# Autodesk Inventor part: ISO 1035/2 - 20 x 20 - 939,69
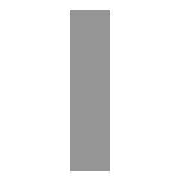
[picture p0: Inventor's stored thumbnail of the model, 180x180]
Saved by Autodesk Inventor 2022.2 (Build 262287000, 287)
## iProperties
IsCustomPart: 1
Created: 2025-02
Part Number: ISO 1035/2 - 20 x 20 - 939,69
Material: Acciaio, Dolce
Description: Barre in acciaio laminate a caldo - Parte 2: barre quadre
Document SubType Name: Modeling
Standard: ISO 1035/2
Designer: 18907419
Standard Revision: First edition 1980-10-15
Standards Organization: ISO
Language: it-IT
Size Designation: 20x 20
Categories: <MemberInstance><Categories><Category DisplayName="Forme strutturali" InternalName="089c4875-fa83-4c05-b084-43b9cc11f5ed" Mnemonic="GRDR"><CategoryParameter Dis
Stock Number: 20x 20
Density: 7.85 g/cm^3
Appearance: Semilucidato
_CCFamilyMember: 168
_CCFamilyDisplayName: ISO 1035/2 - 1980 - Barre in acciaio laminate a caldo - Parte 2: barre quadre
_FrameMemberDoc: Frame Member File
_Version: 15.0.0
_GetPNFromCC: 1
G_L: 939,693 mm
G_W: 20,000 mm
G_H: 20,000 mm
+9CC89346-D58E-49AB-A0AD-2FBC8E4EAC78+CUTDETAIL1: Angolo retto 45,00 gr
+C2A38097-E8B2-4737-A28E-4EEA481CF980+CUTDETAIL2: Angolo di taglio 90,00 gr
Author: 18907419
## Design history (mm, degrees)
node "Piano iniziale"
node "Piano finale"
sketch "Schizzo"
  geometry: L1 (10, -10)-(-10, -10); L2 (-10, -10)-(-10, 10); L3 (-10, 10)-(10, 10); L4 (10, 10)-(10, -10); L5 (-6, 0)-(8, 0); L6 (0, -30)-(0, 40); L7 (0, 54)-(0, -44) reference; L8 (-14, 0)-(14, 0) reference
  constraints: 12 end point, 2 collinear, 2 parallel, 1 horizontal, 1 perpendicular
  dimensions: "d0" = 20 distance between parallel lines of L3 L1 (= G_W); "d1" = 20 distance between parallel lines of L4 L2 (= G_H); "d4" = 10 distance between parallel lines of L6 L4 (= 0.5 x d1); "d5" = 10 distance between parallel lines of L5 L3 (= 0.5 x d0)
extrude "Corpo" new body sketch "Schizzo" stored distance "d2" = 939.69262 (= G_L); taper "d3" = 0 deg
node "Driven Length"
  sketch "Sketch3"
    geometry: L1 (0, 0)-(10, 0) reference
    constraints: 2 end point, 1 horizontal
  workplane "Work Plane3"
  sketch "Sketch4"
    geometry: L1 (-2, 10)-(12, 10) reference; L2 (-2, 949.693)-(12, 949.693) reference
    dimensions: "d9" = 939.69262 dimension on L1 L2 (derived)
node "Piano di lavoro4"
feature "Divisione1"
node "Piano di lavoro5"
feature "Divisione2"
body "Solid1"
other parameters: "G_W" = 20 [user parameter; used in 1 equation term], "G_H" = 20 [user parameter; used in 1 equation term], "G_L" = 939.69262 (= d9) [user parameter; used in 1 equation term], "d7" = 949.69262 (= G_OFFSET_END + B_L), "B_L" = 939.69262 [user parameter; used in 1 equation term], "d8" = 90 deg
